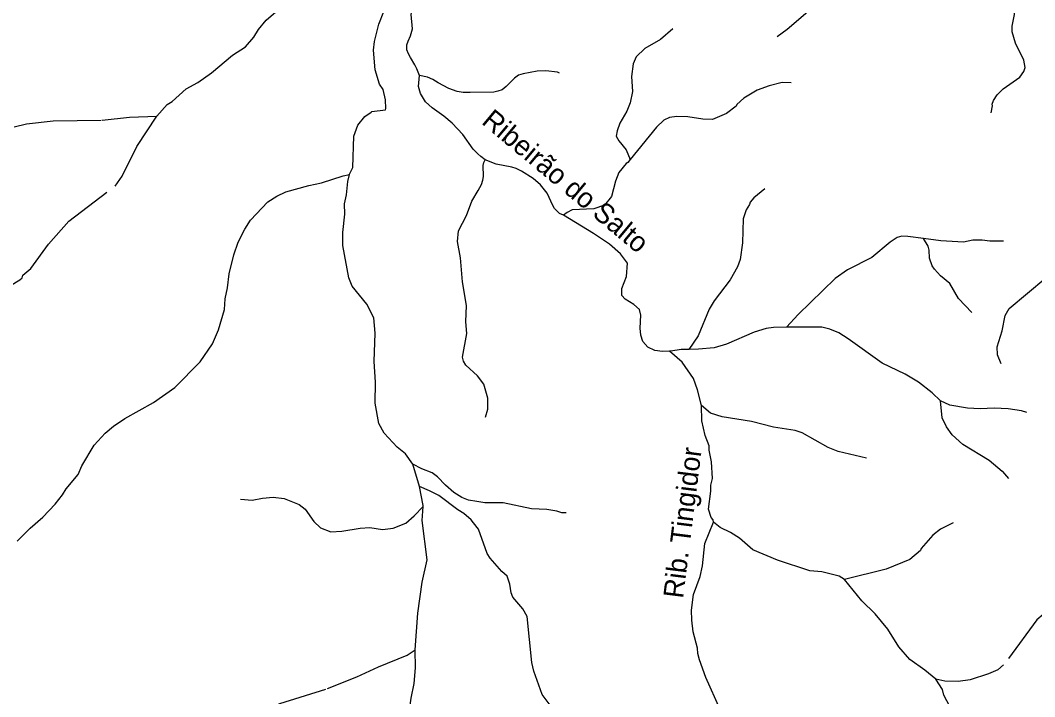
# Model space of a CAD drawing. Extents: x 280.4 to 335.6, y 8893.9 to 8949.5.
# Drawn here: x 284.9 to 293.02, y 8937.49 to 8942.9 of the extents above; entities that cross this region are included whole.
import ezdxf
from ezdxf.enums import TextEntityAlignment as Align

# ---------------------------------------------------------------- set-up
doc = ezdxf.new("R2010")
doc.units = 0
doc.header["$LTSCALE"] = 0.064
doc.linetypes.add('LONG_DASHED', pattern=[7.5, 6, -1.5])
doc.layers.add('61', color=7, linetype='Continuous')
doc.layers.add('7', color=7, linetype='Continuous', lineweight=25)
doc.layers.add('9', color=7, linetype='LONG_DASHED', lineweight=25)

msp = doc.modelspace()

# ---------------------------------------------------------------- linework, layer by layer
at = {"layer": '7'}
for points in [[(290.9613, 8942.7737), (291.0429, 8942.832), (291.2085, 8942.9745), (291.2689, 8943.0524), (291.2908, 8943.1029), (291.2997, 8943.1769), (291.2705, 8943.249), (291.2629, 8943.3121), (291.2808, 8943.37), (291.3013, 8943.4039), (291.3077, 8943.4349), (291.3077, 8943.5128), (291.2571, 8943.6995), (291.2566, 8943.759), (291.2758, 8943.8461), (291.3084, 8943.9147), (291.3201, 8943.9235), (291.3202, 8943.9458)], [(292.675, 8942.1621), (292.6856, 8942.2168), (292.6821, 8942.2327), (292.6931, 8942.2615), (292.7237, 8942.3074), (292.7726, 8942.3556), (292.905, 8942.4481), (292.9357, 8942.4931), (292.9469, 8942.5252), (292.9357, 8942.5827), (292.8699, 8942.7209), (292.843, 8942.8105), (292.8433, 8942.856), (292.8622, 8942.9493), (292.8604, 8942.989), (292.8304, 8943.1009), (292.8367, 8943.2345), (292.8461, 8943.3023), (292.824, 8943.4112), (292.8178, 8943.4152), (292.8205, 8943.4374), (292.8077, 8943.571), (292.7562, 8943.6877), (292.7294, 8943.7914)], [(288.0977, 8942.4614), (288.0881, 8942.4878), (288.0772, 8942.5143), (288.0616, 8942.547), (288.026, 8942.6043), (288.0101, 8942.6352), (287.9974, 8942.6667), (287.9961, 8942.7076), (288.007, 8942.7355), (288.0276, 8942.7778), (288.0417, 8942.8339), (288.0309, 8942.9505), (288.045, 8943.0074), (288.0602, 8943.0374), (288.1816, 8943.1558), (288.2223, 8943.209), (288.2451, 8943.2673), (288.2484, 8943.3231), (288.206, 8943.4772)], [(290.1265, 8942.834), (290.0283, 8942.7491), (289.9023, 8942.6766), (289.8327, 8942.6117), (289.8094, 8942.5533), (289.7965, 8942.4532), (289.8044, 8942.334), (289.7855, 8942.242), (289.758, 8942.1766), (289.703, 8942.0789), (289.6799, 8942.0172), (289.6719, 8941.9753), (289.6935, 8941.9384), (289.7532, 8941.8662), (289.7851, 8941.7876)], [(289.2184, 8942.4793), (289.2025, 8942.4884), (289.1096, 8942.498), (289.0406, 8942.4947), (288.9299, 8942.4751), (288.8925, 8942.4644), (288.8582, 8942.4407), (288.7937, 8942.3739), (288.76, 8942.3475), (288.7247, 8942.3355), (288.6944, 8942.3269), (288.5043, 8942.3241), (288.4493, 8942.3246), (288.3999, 8942.3319), (288.3346, 8942.3571), (288.2486, 8942.4036), (288.2066, 8942.4301), (288.1626, 8942.4468), (288.0977, 8942.4614)], [(288.6236, 8941.785), (288.5909, 8941.8117), (288.5664, 8941.8333), (288.5295, 8941.8715), (288.445, 8941.9877), (288.3608, 8942.08), (288.2947, 8942.1365), (288.2011, 8942.2009), (288.1476, 8942.2501), (288.1057, 8942.3179), (288.0903, 8942.3733), (288.0977, 8942.4614)], [(291.0739, 8942.4022), (291.0028, 8942.4049), (290.8983, 8942.3795), (290.8023, 8942.3444), (290.6941, 8942.2792), (290.6393, 8942.229), (290.6333, 8942.2157), (290.5572, 8942.1575), (290.444, 8942.1095), (290.3672, 8942.1117), (290.2458, 8942.1301), (290.1595, 8942.1333), (290.1011, 8942.1234), (290.0539, 8942.1029), (289.9958, 8942.0477), (289.7851, 8941.7876)], [(288.6261, 8939.7239), (288.6449, 8939.7889), (288.6464, 8939.8782), (288.615, 8939.9906), (288.564, 8940.0565), (288.4707, 8940.1407), (288.4516, 8940.1734), (288.4441, 8940.205), (288.4769, 8940.3941), (288.4708, 8940.4892), (288.4738, 8940.6181), (288.442, 8940.81), (288.4275, 8941.0019), (288.4036, 8941.1305), (288.412, 8941.2179), (288.4745, 8941.3399), (288.5186, 8941.4536), (288.5694, 8941.5394), (288.5944, 8941.5885), (288.5946, 8941.589), (288.6055, 8941.6236), (288.6108, 8941.6524), (288.6082, 8941.7408), (288.6133, 8941.7632), (288.6236, 8941.785)], [(289.2516, 8941.3424), (289.2205, 8941.3563), (289.1996, 8941.3739), (289.1794, 8941.3961), (289.1651, 8941.421), (289.1199, 8941.5176), (289.0687, 8941.5847), (289.0095, 8941.6359), (288.9144, 8941.6947), (288.8729, 8941.7161), (288.8385, 8941.7283), (288.7121, 8941.7516), (288.6236, 8941.785)], [(289.7851, 8941.7876), (289.7655, 8941.7634), (289.752, 8941.7573), (289.6941, 8941.6839), (289.6668, 8941.6154), (289.6347, 8941.4922), (289.5806, 8941.4239), (289.4941, 8941.3929), (289.3215, 8941.3848), (289.2797, 8941.3643), (289.2516, 8941.3424)], [(290.8632, 8941.5534), (290.7747, 8941.4819), (290.7452, 8941.4473), (290.7411, 8941.4277), (290.7148, 8941.3863), (290.6903, 8941.3122), (290.684, 8941.1216), (290.6649, 8940.9873), (290.6437, 8940.9284), (290.5858, 8940.825), (290.459, 8940.6562), (290.4185, 8940.5895), (290.3286, 8940.3751), (290.2553, 8940.2679)], [(290.0993, 8940.2529), (290.0444, 8940.2504), (289.9819, 8940.2587), (289.927, 8940.2867), (289.8859, 8940.3319), (289.8702, 8940.3814), (289.8651, 8940.439), (289.8715, 8940.5413), (289.8591, 8940.5871), (289.8156, 8940.6284), (289.7446, 8940.6694), (289.7182, 8940.6996), (289.7197, 8940.7554), (289.755, 8940.8508), (289.7628, 8940.958), (289.7068, 8941.033), (289.6188, 8941.1113), (289.4924, 8941.1967), (289.2516, 8941.3424)], [(292.1347, 8941.1554), (292.0073, 8941.1724), (291.961, 8941.1737), (291.9224, 8941.1627), (291.8669, 8941.1253), (291.7197, 8941.0023), (291.525, 8940.9058), (291.4261, 8940.8363), (291.1296, 8940.5479), (291.038, 8940.4446)], [(292.521, 8940.5619), (292.4128, 8940.6766), (292.3456, 8940.7947), (292.2707, 8940.8568), (292.2205, 8940.9089), (292.203, 8940.9363), (292.1811, 8940.9994), (292.1777, 8941.0627), (292.1696, 8941.0954), (292.1347, 8941.1554)], [(292.7749, 8941.1349), (292.6657, 8941.1339), (292.6031, 8941.1416), (292.5274, 8941.1418), (292.4547, 8941.1277), (292.2729, 8941.137), (292.1347, 8941.1554)], [(292.7541, 8940.1519), (292.7272, 8940.2233), (292.7234, 8940.2875), (292.763, 8940.4174), (292.7873, 8940.5392), (292.8183, 8940.5941), (293.1138, 8940.8416), (293.3502, 8940.9921), (293.457, 8941.0833)], [(291.038, 8940.4446), (290.9337, 8940.4441), (290.8727, 8940.4349), (290.7768, 8940.4061), (290.5574, 8940.3087), (290.4576, 8940.2799), (290.3336, 8940.2687), (290.2553, 8940.2679)], [(292.2701, 8939.8571), (292.2018, 8939.9211), (292.0941, 8940.0064), (291.9879, 8940.0699), (291.8028, 8940.157), (291.5317, 8940.3527), (291.4548, 8940.3997), (291.3844, 8940.4301), (291.3205, 8940.446), (291.038, 8940.4446)], [(290.2553, 8940.2679), (290.1931, 8940.2673), (290.1111, 8940.2534), (290.0993, 8940.2529)], [(292.9611, 8939.7635), (292.9184, 8939.7759), (292.8104, 8939.792), (292.699, 8939.7983), (292.5877, 8939.7921), (292.4864, 8939.7972), (292.3448, 8939.8222), (292.2701, 8939.8571)], [(292.8161, 8939.2331), (292.7691, 8939.2903), (292.7634, 8939.289), (292.6596, 8939.3774), (292.449, 8939.5067), (292.3625, 8939.5832), (292.3165, 8939.647), (292.2836, 8939.7193), (292.2701, 8939.8571)]]:
    msp.add_lwpolyline(points, dxfattribs=at)
at = {"layer": '9'}
msp.add_line((288.0984, 8939.1702), (288.0443, 8939.3492), dxfattribs=at)
for points in [[(287.5388, 8941.6687), (287.5395, 8941.6717), (287.5646, 8941.7255), (287.5726, 8941.9754), (287.6056, 8942.0629), (287.6615, 8942.1314), (287.7108, 8942.1683), (287.7183, 8942.1739), (287.8259, 8942.1864), (287.8304, 8942.1961), (287.8278, 8942.2653), (287.8073, 8942.3493), (287.7795, 8942.3918), (287.7436, 8942.5051), (287.7296, 8942.6628), (287.7387, 8942.7326), (287.7729, 8942.8722), (287.8131, 8942.974), (287.9121, 8943.1179), (288.1192, 8943.3318), (288.206, 8943.4772)], [(285.9953, 8942.1346), (286.0797, 8942.2288), (286.1198, 8942.2531), (286.2311, 8942.355), (286.324, 8942.4057), (286.4335, 8942.4813), (286.6027, 8942.6227), (286.7066, 8942.69), (286.7738, 8942.7667), (286.8106, 8942.8306), (286.8718, 8942.9044), (286.9485, 8942.9702), (287.008, 8943.0359), (287.0774, 8943.0965), (287.1356, 8943.1704), (287.2006, 8943.3047), (287.2201, 8943.3294)], [(284.1233, 8940.4486), (284.2208, 8940.4731), (284.3112, 8940.5119), (284.3798, 8940.5496), (284.5925, 8940.6904), (284.6643, 8940.7243), (284.8233, 8940.7807), (284.9003, 8940.8244), (284.9167, 8940.8396), (284.9242, 8940.8609), (284.9885, 8940.9159), (285.1286, 8941.1116), (285.2908, 8941.2948), (285.6612, 8941.5759), (285.7178, 8941.6546), (285.8371, 8941.8925), (285.9953, 8942.1346)], [(284.8537, 8942.0502), (284.9521, 8942.0744), (285.1672, 8942.098), (285.5582, 8942.1034), (285.7775, 8942.1271), (285.9953, 8942.1346)], [(284.8772, 8938.7313), (284.9816, 8938.8361), (285.0844, 8938.9233), (285.1822, 8939.029), (285.2417, 8939.1044), (285.2705, 8939.1511), (285.3655, 8939.2655), (285.3951, 8939.3349), (285.4953, 8939.5007), (285.5818, 8939.5964), (285.6501, 8939.6536), (285.74, 8939.7132), (285.9687, 8939.8412), (286.1406, 8939.9617), (286.3425, 8940.1669), (286.4407, 8940.3127), (286.4907, 8940.4237), (286.5385, 8940.5878), (286.5434, 8940.6733), (286.5611, 8940.7612), (286.574, 8940.8722), (286.6125, 8941.0257), (286.6475, 8941.1273), (286.6997, 8941.2298), (286.7451, 8941.3017), (286.8834, 8941.4502), (286.9561, 8941.4952), (287.0282, 8941.5282), (287.2124, 8941.5808), (287.3151, 8941.601), (287.488, 8941.658), (287.5388, 8941.6687)], [(288.0443, 8939.3492), (287.9874, 8939.4319), (287.9196, 8939.4857), (287.8172, 8939.596), (287.7723, 8939.6738), (287.7447, 8939.8376), (287.7477, 8940.0064), (287.7349, 8940.171), (287.7428, 8940.3965), (287.7319, 8940.5213), (287.6781, 8940.6289), (287.5595, 8940.7734), (287.5342, 8940.8407), (287.4859, 8941.1003), (287.4855, 8941.2041), (287.5014, 8941.3505), (287.4985, 8941.4337), (287.5142, 8941.5065), (287.5256, 8941.6111), (287.5388, 8941.6687)], [(290.3562, 8939.8195), (290.3237, 8939.9451), (290.2929, 8940.0357), (290.2009, 8940.1658), (290.0993, 8940.2529)], [(291.6766, 8939.3968), (291.4495, 8939.4496), (291.3694, 8939.4821), (291.1621, 8939.5998), (291.1056, 8939.6177), (290.9318, 8939.6449), (290.7572, 8939.6916), (290.5226, 8939.7283), (290.4275, 8939.7575), (290.3562, 8939.8195)], [(290.4531, 8938.8847), (290.4484, 8938.9021), (290.4324, 8938.9221), (290.4124, 8938.9875), (290.4312, 8939.1332), (290.4314, 8939.1804), (290.4456, 8939.2348), (290.4375, 8939.3675), (290.4189, 8939.4603), (290.4183, 8939.4961), (290.3854, 8939.5789), (290.3601, 8939.697), (290.3562, 8939.8195)], [(289.2739, 8938.9581), (289.2391, 8938.9598), (289.1973, 8938.9729), (289.1192, 8938.9844), (288.9959, 8938.991), (288.7688, 8939.0385), (288.6227, 8939.0389), (288.5585, 8939.0495), (288.4922, 8939.0604), (288.4364, 8939.0808), (288.373, 8939.122), (288.3059, 8939.1811), (288.244, 8939.2477), (288.2003, 8939.2801), (288.1169, 8939.3113), (288.0443, 8939.3492)], [(289.2712, 8937.2499), (289.0816, 8937.5051), (289.013, 8937.6914), (288.9986, 8937.7608), (288.9597, 8938.1287), (288.9248, 8938.191), (288.8462, 8938.2847), (288.8324, 8938.3183), (288.8225, 8938.3887), (288.8017, 8938.4511), (288.7583, 8938.4898), (288.6654, 8938.5955), (288.6414, 8938.6334), (288.5712, 8938.8275), (288.5592, 8938.8425), (288.5112, 8938.9023), (288.4535, 8938.9536), (288.4063, 8938.9818), (288.2527, 8939.0971), (288.1795, 8939.1363), (288.0984, 8939.1702)], [(288.1284, 8939.0097), (288.1292, 8939.0186), (288.0984, 8939.1702)], [(286.6666, 8939.068), (286.7582, 8939.0612), (286.841, 8939.0771), (286.926, 8939.0834), (287.0157, 8939.0732), (287.1364, 8939.0266), (287.1832, 8938.9891), (287.2516, 8938.8906), (287.3068, 8938.8399), (287.3888, 8938.807), (287.4783, 8938.8118), (287.6231, 8938.8372), (287.7004, 8938.8403), (287.8038, 8938.8246), (287.8869, 8938.8374), (287.9892, 8938.8774), (288.057, 8938.9354), (288.1284, 8939.0097)], [(288.0644, 8937.861), (288.0867, 8938.1555), (288.1199, 8938.4034), (288.1601, 8938.583), (288.1189, 8938.898), (288.1284, 8939.0097)], [(290.6283, 8936.5343), (290.6582, 8936.6975), (290.6582, 8936.869), (290.5585, 8937.1092), (290.548, 8937.1523), (290.5325, 8937.3064), (290.5051, 8937.3829), (290.3911, 8937.6417), (290.3394, 8937.7822), (290.3274, 8937.8314), (290.3254, 8937.8757), (290.2907, 8938.0065), (290.2779, 8938.0984), (290.2765, 8938.1809), (290.2922, 8938.3063), (290.3465, 8938.4503), (290.3642, 8938.5334), (290.3837, 8938.7133), (290.4531, 8938.8847)], [(291.5014, 8938.426), (291.4573, 8938.4525), (291.3189, 8938.4854), (291.224, 8938.4941), (290.9647, 8938.58), (290.768, 8938.6635), (290.6593, 8938.7561), (290.5872, 8938.8004), (290.5058, 8938.8403), (290.4531, 8938.8847)], [(292.3701, 8938.8787), (292.2698, 8938.8292), (292.2082, 8938.7804), (292.1141, 8938.6728), (292.1087, 8938.6566), (292.0235, 8938.5844), (291.8338, 8938.5079), (291.5014, 8938.426)], [(292.2311, 8937.6276), (292.1443, 8937.6986), (292.0242, 8937.7846), (291.9372, 8937.8862), (291.8481, 8938.0279), (291.7464, 8938.15), (291.6391, 8938.2547), (291.5014, 8938.426)], [(293.5753, 8938.2188), (293.2698, 8938.1897), (293.1763, 8938.1716), (293.0907, 8938.1445), (293.04, 8938.1024), (292.7751, 8937.7411), (292.7273, 8937.7009), (292.6527, 8937.6692), (292.5064, 8937.6213), (292.4104, 8937.608), (292.3048, 8937.6118), (292.2311, 8937.6276)], [(286.86, 8937.3667), (286.9819, 8937.4331), (287.3632, 8937.5528), (287.5977, 8937.6453), (287.7712, 8937.7255), (288.0004, 8937.8186), (288.0644, 8937.861)], [(287.9256, 8936.9331), (287.9492, 8936.9999), (288.0006, 8937.2435), (288.031, 8937.4755), (288.0551, 8937.5918), (288.0676, 8937.7185), (288.0644, 8937.861)], [(293.6747, 8937.2512), (293.5398, 8937.233), (293.3081, 8937.1642), (293.1459, 8937.0928), (293.0597, 8937.0876), (293.0093, 8937.0766), (292.7857, 8937.0953), (292.6836, 8937.1357), (292.5855, 8937.2261), (292.365, 8937.369), (292.2951, 8937.4986), (292.2848, 8937.5435), (292.2311, 8937.6276)]]:
    msp.add_lwpolyline(points, dxfattribs=at)

# ---------------------------------------------------------------- texts
at = {"layer": '61'}
for s, rotation, p in [('Ribeirão do Salto', 320.194, (289.2182, 8941.5548)), ('Rib. Tingidor', 82.875, (290.2836, 8938.8704))]:
    msp.add_text(s, height=0.16, rotation=rotation, dxfattribs=at).set_placement(p, align=Align.CENTER)

doc.saveas('drawing.dxf')
